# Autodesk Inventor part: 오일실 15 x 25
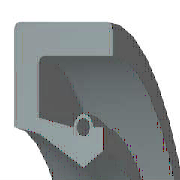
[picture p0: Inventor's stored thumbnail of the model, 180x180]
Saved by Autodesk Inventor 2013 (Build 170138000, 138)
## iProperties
IsCustomPart: 0
Created: 2015-10
Part Number: 오일실 15 x 25
Material: 고무
Description: 오일-실
Document SubType Name: Modeling
Standard: KS B 2804
Designer: mdu
Standards Organization: KS
Language: ko-KR
Size Designation: S - 15 25 7
Categories: <MemberInstance><Categories><Category DisplayName="샤프트 부품" InternalName="7f7aeb1f-a693-4053-b835-cee3144e0d98" Mnemonic="SHFT"><Category DisplayName="실링" Intern
Density: 0.93 g/cm^3
Mass: 1.19654 g
Surface Area: 20.4621 cm^2
Volume: 1.28661 cm^3
Author: mdu
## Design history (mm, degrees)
revolve "본체" stored, may be unused: angle "d17" = 90 deg
revolve "스프링1" stored, may be unused: angle "d18" = 90 deg
body "Solid1"
sketch "스케치1"
  geometry: L1 (0, 12.5)-(7, 12.5); L2 (7, 12.5)-(7, 11.25); L3 (7, 11.25)-(1.75, 11.25); L4 (0, 12.5)-(0, 9.6); L5 (0, 9.6)-(1.75, 9.25); L6 (1.75, 9.25)-(4.9, 7.5); L7 (4.9, 7.5)-(0, 7.5); L8 (6.3, 8.375)-(6.3, 9.6); L9 (0, 0)-(9.586, 0) reference; L10 (4.9, 7.5)-(6.3, 8.375); L11 (0, 18)-(0, -3) reference; L12 (-1.917, 0)-(11.503, 0) reference; L13 (4.2, 9.6)-(1.75, 10.09); L14 (1.75, 10.09)-(1.75, 11.25); L15 (6.3, 9.6)-(5.6, 9.6); C1 r 0.455 at (4.9, 9.6); A1 r 0.7 centre (4.9, 9.6) between (5.6, 9.6) and (4.2, 9.6)
  constraints: 26 end point, 5 horizontal alignment, 4 perpendicular, 2 centre point, 2 collinear, 2 horizontal, 2 parallel, 2 point on circle, 2 point on line, 2 vertical alignment, 1 coincident
  dimensions: "d0" = 25 diameter of L1 L9 (= SD2); "d1" = 16.75 diameter of L8.start L9 (= ABDM); "d2" = 1.25 distance of L1.end L2.end (computed from SD); "d3" = 0.91 diameter of C1 (= SPDI); "d4" = 1.4 diameter of A1 (= SPDA); "d5" = 15 diameter of L6.end L9 (= NND); "d6" = 18.5 diameter of L5.end L9 (= TKDM); "d7" = 19.2 diameter of L4.end L9 (= HLDM); "d8" = 4.9 distance from line of C1.centre L4 (= SPDST); "d9" = 6.3 distance between parallel lines of L8 L4 (= SDI); "d10" = 7 distance between parallel lines of L2 L4 (= SWDT); "d12" = 1.75 distance between parallel lines of L14 L4 (= SD)
fillet "모깎기1" dims "d11" = 0.3 (= RR)
other parameters: "SD2" = 25 [user parameter; used in 1 equation term], "SWDT" = 7 [user parameter; used in 1 equation term], "RR" = 0.3 [user parameter; used in 1 equation term], "SD" = 1.75 [user parameter; used in 2 equation terms], "NND" = 15 [user parameter; used in 1 equation term], "SPDA" = 1.4 [user parameter; used in 1 equation term], "SPDI" = 0.91 [user parameter; used in 1 equation term], "TKDM" = 18.5 [user parameter; used in 1 equation term], "HLDM" = 19.2 [user parameter; used in 1 equation term], "ABDM" = 16.75 [user parameter; used in 1 equation term], "SDI" = 6.3 [user parameter; used in 1 equation term], "SPDST" = 4.9 [user parameter; used in 1 equation term], "d13" = 0, "d14" = 0, "d15" = 0, "LAB" = 0.35 [user parameter]
